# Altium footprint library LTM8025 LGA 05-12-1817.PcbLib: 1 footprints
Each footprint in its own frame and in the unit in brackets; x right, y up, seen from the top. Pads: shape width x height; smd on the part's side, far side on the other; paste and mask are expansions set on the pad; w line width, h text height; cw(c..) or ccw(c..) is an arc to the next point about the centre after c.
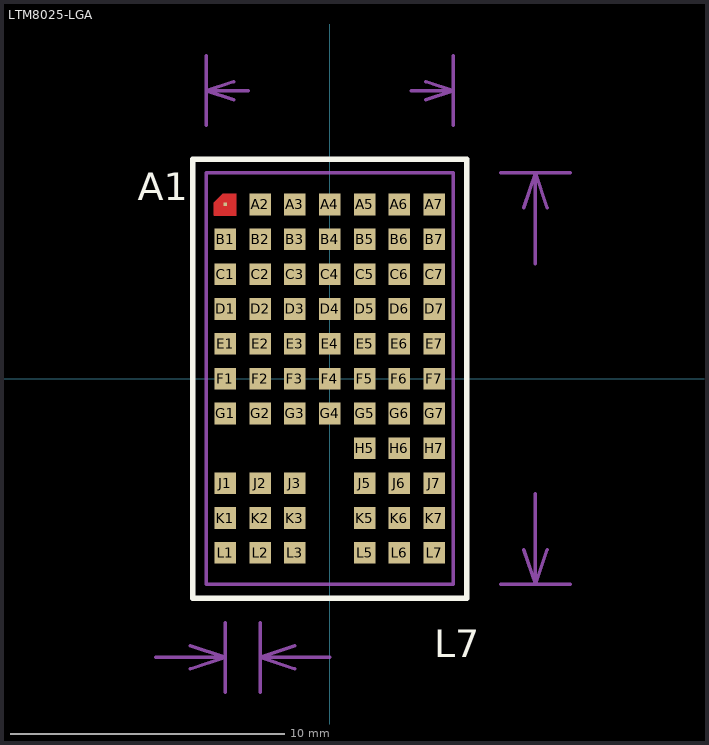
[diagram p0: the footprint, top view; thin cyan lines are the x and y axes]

## LTM8025-LGA [mil]
pads (70):
  rect 5x5 smd paste-3.5 mask-3: A1(-150,250)
  rect 31x31 smd paste-3.5 mask-3: A2(-100,250) A3(-50,250) A4(0,250) A5(50,250) A6(100,250) A7(150,250) B1(-150,200) B2(-100,200) B3(-50,200) B4(0,200) B5(50,200) B6(100,200) B7(150,200) C1(-150,150) C2(-100,150) C3(-50,150) C4(0,150) C5(50,150) C6(100,150) C7(150,150) D1(-150,100) D2(-100,100) D3(-50,100) D4(0,100) D5(50,100) D6(100,100) D7(150,100) E1(-150,50) E2(-100,50) E3(-50,50) E4(0,50) E5(50,50) E6(100,50) E7(150,50) F1(-150,0) F2(-100,0) F3(-50,0) F4(0,0) F5(50,0) F6(100,0) F7(150,0) G1(-150,-50) G2(-100,-50) G3(-50,-50) G4(0,-50) G5(50,-50) G6(100,-50) G7(150,-50) H5(50,-100) H6(100,-100) H7(150,-100) J1(-150,-150) J2(-100,-150) J3(-50,-150) J5(50,-150) J6(100,-150) J7(150,-150) K1(-150,-200) K2(-100,-200) K3(-50,-200) K5(50,-200) K6(100,-200) K7(150,-200) L1(-150,-250) L2(-100,-250) L3(-50,-250) L5(50,-250) L6(100,-250) L7(150,-250)
TopLayer:
  region: -165.5,234.5 -134.5,234.5 -134.5,265.5 -152.5,265.5 -165.5,252.5
  lines w0.39: -165.5,234.5 -165.5,252.5 -152.5,265.5 -134.5,265.5 -134.5,234.5 -165.5,234.5
TopOverlay:
  lines w8: -196.85,-314.96 -196.85,314.96 196.85,314.96 196.85,-314.96 -196.85,-314.96
  text "L7" at 150,-400 h40
  text "A1" at -275.59,255.91 h40
Mechanical16:
  lines w5: -250,-400 -150,-400 ; -200,-416.67 -150,-400 ; -200,-383.33 -150,-400 ; -177.17,363.39 -177.17,463.39 ; -150,-450 -150,-350 ; -137.8,400.26 -177.17,413.39 ; -137.8,426.51 -177.17,413.39 ; -116.67,413.39 -177.17,413.39 ; -100,-450 -100,-350 ; -50,-416.67 -100,-400 ; -50,-383.33 -100,-400 ; 0,-400 -100,-400 ; 116.67,413.39 177.17,413.39 ; 137.8,400.26 177.17,413.39 ; 137.8,426.51 177.17,413.39 ; 177.17,363.39 177.17,463.39 ; 245.28,-295.28 345.28,-295.28 ; 245.28,295.28 345.28,295.28 ; 278.61,-245.28 295.28,-295.28 ; 278.61,245.28 295.28,295.28 ; 295.28,-164.95 295.28,-295.28 ; 295.28,164.95 295.28,295.28 ; 311.94,-245.28 295.28,-295.28 ; 311.94,245.28 295.28,295.28 ; -177.17,-295.28 177.17,-295.28 177.17,295.28 -177.17,295.28 -177.17,-295.28
  text "15 (mm)" at 325.27,-154.95 h50
  text "9 (mm)" at -106.67,388.71 h39.37
  text "1.27 (mm)" at -325.77,-519.97 h50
